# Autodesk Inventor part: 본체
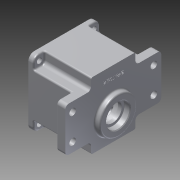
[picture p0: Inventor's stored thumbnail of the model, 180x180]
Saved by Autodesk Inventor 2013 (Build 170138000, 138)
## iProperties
Created: 2015-07
Part Number: 본체
Material: 알루미늄 6061
Document SubType Name: Modeling
Designer: user
Density: 1 g/cm^3
Author: user
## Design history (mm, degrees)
sketch "스케치1"
  geometry: L1 (-65, -30)-(65, -30); L2 (65, -30)-(65, 30); L3 (65, 30)-(-65, 30); L4 (-65, 30)-(-65, -30); 3 further points
  constraints: 8 end point, 2 midpoint, 2 parallel, 1 horizontal, 1 horizontal alignment, 1 perpendicular, 1 vertical alignment
  dimensions: "d0" = 130 distance of L3.end L2.end; "d1" = 60 distance of L2.end L1.end
extrude "돌출1" new body sketch "스케치1" distance "d2" = 12; taper "d3" = 0 deg
fillet "모깎기1" dims "d4" = 5
sketch "스케치2"
  geometry: L1 (25, 65)-(-25, 65) reference; L2 (0, 0)-(0, -55); L3 (0, -55)-(-17.5, -55); L4 (0, -55)-(17.5, -55); L5 (0, 0)-(13, 0); C1 r 4.5 at (-17.5, -55); C2 r 4.5 at (17.5, -55); C3 r 4.5 at (-17.5, 55); C4 r 4.5 at (17.5, 55)
  constraints: 8 end point, 4 centre point, 2 coincident, 2 perpendicular, 2 symmetric about line, 1 collinear, 1 parallel, 2 other
  dimensions: "d5" = 55 distance of L2.start L2.end; "d6" = 17.5 distance of L2.end L3.end; "d7" = 9 diameter of C1; "d8" = 17.5 distance of L2.end L4.end; "d9" = 9 diameter of C2
extrude "돌출2" cut sketch "스케치2" distance "d10" = 12; taper "d11" = 0 deg
sketch "스케치3"
  geometry: L1 (30, -45)-(-30, -45); L2 (-30, -45)-(-30, 45); L3 (-30, 45)-(30, 45); L4 (30, 45)-(30, -45); 3 further points
  constraints: 8 end point, 2 midpoint, 2 parallel, 1 horizontal, 1 horizontal alignment, 1 perpendicular, 1 vertical alignment
  dimensions: "d12" = 60 distance of L2.end L3.end; "d13" = 90 distance of L1.end L2.end
extrude "돌출3" join sketch "스케치3" distance "d14" = 51; taper "d15" = 0 deg
sketch "스케치4"
  geometry: L1 (45, -45)-(-45, -45); L2 (-45, -45)-(-45, 45); L3 (-45, 45)-(45, 45); L4 (45, 45)-(45, -45); 3 further points
  constraints: 8 end point, 2 midpoint, 2 parallel, 1 horizontal, 1 horizontal alignment, 1 perpendicular, 1 vertical alignment
  dimensions: "d16" = 90 distance of L2.end L3.end; "d17" = 90 distance of L1.end L2.end
extrude "돌출4" join sketch "스케치4" distance "d18" = 7; taper "d19" = 0 deg
sketch "스케치5"
  geometry: L1 (30, -60)-(30, 60) reference; L2 (0, 0)-(30, 0); L3 (30, 0)-(30, 30); L4 (30, 0)-(30, -30); L5 (45, -45)-(45, 45) reference; L6 (-30, -45)-(-30, 45) reference; L7 (-30, 45)-(-45, 45) reference; L8 (-45, 45)-(-45, -45) reference; L9 (-45, -45)-(-30, -45) reference; L10 (30, 45)-(30, -45) reference; L11 (30, -45)-(45, -45) reference; L12 (45, -45)-(45, 45) reference; L13 (45, 45)-(30, 45) reference; L14 (30, 30)-(45, 30); L15 (45, 30)-(45, -30); L16 (30, -30)-(45, -30); L17 (0, 0)-(0, -15); L18 (-30, -30)-(-45, -30); L19 (-45, 30)-(-45, -30); L20 (-30, 30)-(-30, -30); L21 (-30, 30)-(-45, 30)
  constraints: 22 end point, 4 point on line, 4 symmetric about line, 3 perpendicular, 1 midpoint
  dimensions: "d20" = 30 distance of L2.end L3.end; "d21" = 30 distance of L2.end L4.end
extrude "돌출5" join sketch "스케치5" stored distance "d22" = 7; taper "d23" = 0 deg
sketch "스케치7"
  geometry: C1 r 40 at (0, 0); 1 further point
  constraints: 1 centre point, 1 coincident
  dimensions: "d27" = 80 diameter of C1
extrude "돌출7" cut sketch "스케치7" distance "d28" = 9; taper "d29" = 0 deg
sketch "스케치10"
  geometry: C1 r 40 at (0, 0) reference; C2 r 39 at (0, 0)
  constraints: 1 centre point, 1 coincident
  dimensions: "d36" = 78 diameter of C2
extrude "돌출10" cut sketch "스케치10" distance "d37" = 52; taper "d38" = 0 deg
sketch "스케치11"
  geometry: L1 (30, 60)-(30, 30) reference; L2 (30, 30)-(45, 30) reference; L3 (45, 30)-(45, -30) reference; L4 (45, -30)-(30, -30) reference; L5 (30, -30)-(30, -60) reference; L6 (25, -65)-(-25, -65) reference; L7 (-30, -60)-(-30, -30) reference; L8 (-30, -30)-(-45, -30) reference; L9 (-45, -30)-(-45, 30) reference; L10 (-45, 30)-(-30, 30) reference; L11 (-30, 30)-(-30, 60) reference; L12 (-25, 65)-(25, 65) reference; L13 (0, 0)-(-11, 0); L14 (0, 0)-(20, 0); C1 r 39 at (0, 0) reference; C2 r 4.5 at (17.5, 55) reference; C3 r 4.5 at (17.5, -55) reference; C4 r 4.5 at (-17.5, -55) reference; C5 r 4.5 at (-17.5, 55) reference; A1 r 5 centre (25, 60) between (30, 60) and (25, 65) reference; A2 r 5 centre (25, -60) between (25, -65) and (30, -60) reference; A3 r 5 centre (-25, -60) between (-30, -60) and (-25, -65) reference; A4 r 5 centre (-25, 60) between (-25, 65) and (-30, 60) reference; A5 r 20.5 centre (-11, 0) between (8.117, 7.402) and (8.117, -7.402); A6 r 14 centre (20, 0) between (8.117, -7.402) and (8.117, 7.402)
  constraints: 4 end point, 4 point on circle, 2 centre point, 2 coincident, 1 collinear, 1 parallel
  dimensions: "d39" = 11 distance of L13.start L13.end; "d42" = 20 distance of L13.start L14.end; "d44" = 41 diameter of A5; "d45" = 28 diameter of A6
extrude "돌출11" join sketch "스케치11" distance "d46" = 7; taper "d47" = 0 deg
sketch "스케치12"
  geometry: C1 r 17.5 at (-11, 0); C2 r 11 at (20, 0); A1 r 20.5 centre (-11, 0) between (8.117, 7.402) and (8.117, -7.402) reference; A2 r 14 centre (20, 0) between (8.117, -7.402) and (8.117, 7.402) reference; 1 further point
  constraints: 2 centre point, 2 coincident
  dimensions: "d48" = 35 diameter of C1; "d49" = 22 diameter of C2
extrude "돌출12" cut sketch "스케치12" distance "d50" = 10; taper "d51" = 0 deg
extrude "돌출13" cut sketch "스케치12" distance "d52" = 7; taper "d53" = 0 deg
sketch "스케치13"
  geometry: C1 r 11 at (0, 0) reference; C2 r 9.5 at (0, 0); 1 further point
  constraints: 1 centre point, 1 coincident
  dimensions: "d54" = 19 diameter of C2
extrude "돌출14" cut sketch "스케치13" distance "d55" = 1; taper "d56" = 0 deg
fillet "모깎기2" dims "d57" = 3
fillet "모깎기3" dims "d58" = 2
sketch "스케치14"
  geometry: L1 (30, -60)-(30, -30) reference; L2 (0, 0)-(11, 0); C1 r 25 at (11, 0)
  constraints: 2 end point, 1 centre point, 1 coincident, 1 perpendicular
  dimensions: "d59" = 11 distance of L2.start L2.end; "d60" = 50 diameter of C1
extrude "돌출15" join sketch "스케치14" distance "d61" = 7; taper "d62" = 0 deg
sketch "스케치15"
  geometry: C1 r 25 at (0, 0) reference; C2 r 16 at (0, 0); 1 further point
  constraints: 1 centre point, 1 coincident
  dimensions: "d63" = 32 diameter of C2
extrude "돌출16" cut sketch "스케치15" distance "d64" = 8; taper "d65" = 0 deg
sketch "스케치16"
  geometry: C1 r 16 at (0, 0) reference; C2 r 12.5 at (0, 0); 1 further point
  constraints: 1 centre point, 1 coincident
  dimensions: "d66" = 25 diameter of C2
extrude "돌출17" cut sketch "스케치16" distance "d67" = 5; taper "d68" = 0 deg
sketch "스케치17"
  geometry: L1 (0, 0)-(-35, 0); L2 (0, 0)-(24.749, 24.749); L3 (0, 0)-(35, 0); A1 r 39 centre (0, 0) between (32.777, 21.134) and (21.134, 32.777) reference; A2 r 35 centre (0, 0) between (21.763, 27.411) and (27.411, 21.763); A3 r 4 centre (24.749, 24.749) between (21.809, 27.462) and (27.462, 21.809); A4 r 3.5 centre (29.836, 19.238) between (32.777, 21.134) and (27.412, 21.762); A5 r 3.5 centre (19.238, 29.836) between (21.762, 27.412) and (21.134, 32.777)
  constraints: 17 point on circle, 6 end point, 4 centre point, 4 tangent, 2 coincident, 2 horizontal, 1 equal length
  dimensions: "d69" = 70 diameter of A2; "d70" = 45 deg angle of L3 L2; "d71" = 8 diameter of A3; "d72" = 7 diameter of A4; "d73" = 7 diameter of A5; "d74" = 5.35816 distance of A3.end A1.start
extrude "돌출18" join sketch "스케치17" distance "d75" = 52; taper "d76" = 0 deg
sketch "스케치18"
  geometry: A1 r 4 centre (24.749, -24.749) between (27.462, -21.809) and (21.809, -27.462) reference; A2 r 4 centre (-24.749, -24.749) between (-21.809, -27.462) and (-27.462, -21.809) reference; A3 r 4 centre (-24.749, 24.749) between (-27.462, 21.809) and (-21.809, 27.462) reference; A4 r 4 centre (24.749, 24.749) between (21.809, 27.462) and (27.462, 21.809) reference; 4 further points
  constraints: 4 coincident
hole "구멍1" sketch "스케치18" at (-24.749, -24.749), (-24.749, 24.749), (24.749, -24.749), (24.749, 24.749) diameter "d80" = 3.459; stored, may be unused: countersink angle "d84" = 90 deg, drill point angle "d86" = 118 deg; dims "d81" = 12, "d82" = 4, "d83" = 2, "d85" = 15
fillet "모깎기4" dims "d87" = 2
fillet "모깎기5" dims "d88" = 2
fillet "모깎기6" dims "d89" = 8
fillet "모깎기7" dims "d90" = 5
fillet "모깎기8" dims "d91" = 2
fillet "모깎기9" dims "d92" = 2
sketch "스케치19"
  geometry: L1 (-45, -28)-(-45, 28) reference; L2 (-43, 30)-(-35, 30) reference; L3 (-45, 0)-(-30, 0); 2 further points
  constraints: 2 end point, 1 coincident, 1 midpoint, 1 parallel, 1 other
  dimensions: "d93" = 15 distance of L3.start L3.end
feature "엠보싱1" sketch "스케치19" dims "d5" = 55, "d6" = 17.5, "d7" = 9, "d8" = 17.5, "d9" = 9, "d94" = 0.5, "d95" = 0
fillet "모깎기10" dims "d96" = 0.3
chamfer "모따기1" distance "d97" = 1; stored, may be unused: second distance "d98" = 2, angle "d99" = 45 deg
fillet "모깎기11" dims "d100" = 0.3
chamfer "모따기2" distance "d101" = 1; stored, may be unused: second distance "d102" = 2, angle "d103" = 45 deg
fillet "모깎기12" dims "d104" = 2
fillet "모깎기13" dims "d105" = 2
sketch "스케치20"
  geometry: L1 (45, -37)-(45, 37) reference; L2 (0, 0)-(0, -11.542); C1 r 40 at (0, 0) reference; C2 r 3.5 at (-37, 37); C3 r 3.5 at (-37, -37); C4 r 3.5 at (37, 37); C5 r 3.5 at (37, -37); A1 r 8 centre (-37, 37) between (-37, 45) and (-45, 37) reference; A2 r 8 centre (-37, -37) between (-45, -37) and (-37, -45) reference
  constraints: 4 centre point, 2 coincident, 2 end point, 2 symmetric about line, 1 parallel, 2 other
  dimensions: "d106" = 7 diameter of C2; "d107" = 7 diameter of C3
extrude "돌출19" cut sketch "스케치20" distance "d108" = 10; taper "d109" = 0 deg
fillet "모깎기14" dims "d110" = 2
node "솔리드1"
pattern_circular "원형 패턴1" dims angle "d78" = 360 deg
node "투영된 루프1"
node "투영된 루프2"
node "절단 모서리 투영1"
